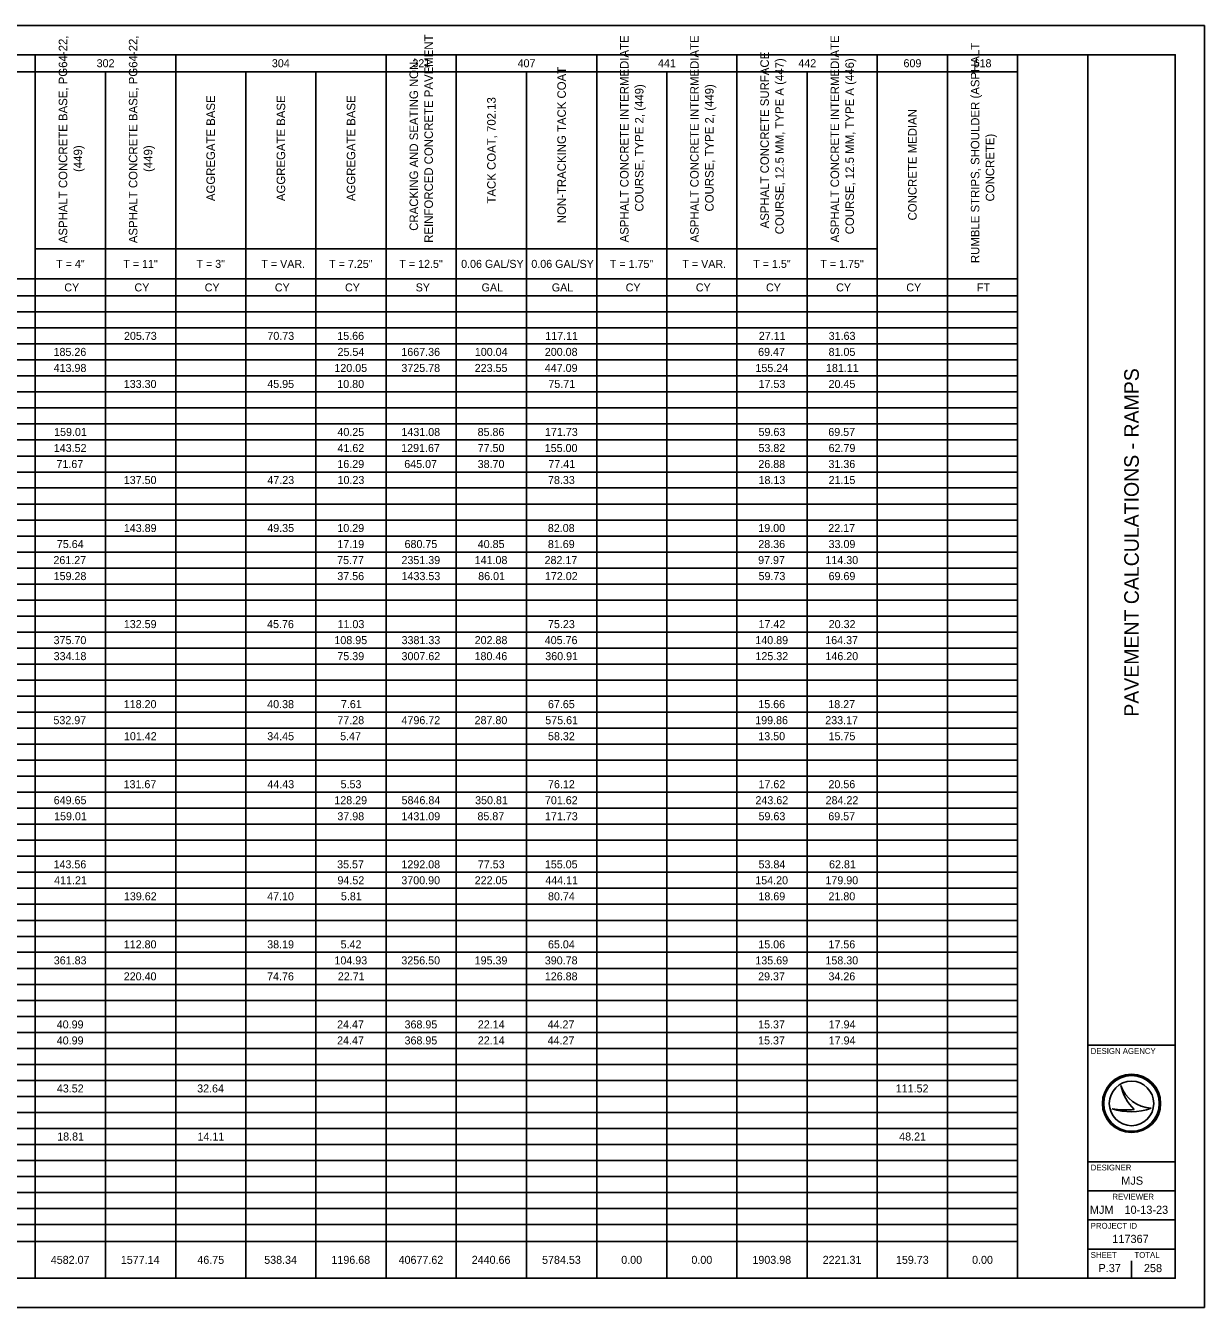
# Model space of a CAD drawing. Extents: x 0 to 34, y 0 to 22.
# Drawn here: x 13.77 to 34, y 0 to 22 of the extents above; entities that cross this region are included whole.
import ezdxf

# ---------------------------------------------------------------- set-up
doc = ezdxf.new("R2010")
doc.units = 0
for name, color, linetype in [('SH_Border', 7, 'Continuous'), ('SH_Cut_Line', 7, 'Continuous'), ('SH_Data', 7, 'Continuous'), ('SH_Text', 7, 'Continuous')]:
    doc.layers.add(name, color=color, linetype=linetype)

msp = doc.modelspace()

# ---------------------------------------------------------------- linework, layer by layer
at = {"layer": 'SH_Border'}
for p, q in [((32, 0.5), (32, 21.5)), ((32, 4.5), (33.5, 4.5)), ((32, 2.5), (33.5, 2.5)), ((32, 2), (33.5, 2)), ((32, 1.5), (33.5, 1.5)), ((32, 1), (33.5, 1))]:
    msp.add_line(p, q, dxfattribs=at)
msp.add_lwpolyline([(1.5, 21.5), (33.5, 21.5), (33.5, 0.5), (1.5, 0.5)], close=True, dxfattribs=at)
at = {"layer": 'SH_Cut_Line'}
msp.add_lwpolyline([(0, 0), (34, 0), (34, 22), (0, 22)], close=True, dxfattribs=at)
at = {"layer": 'SH_Data'}
for p, q in [((32.567, 3.81), (32.567, 3.81)), ((32.417, 3.41), (32.417, 3.41)), ((32.75, 3.5), (32.75, 3.5)), ((33.087, 3.419), (33.087, 3.419)), ((32.375, 0.675), (32.375, 0.675)), ((32.75, 0.5), (32.75, 0.8))]:
    msp.add_line(p, q, dxfattribs=at)
for radius in [0.5, 0.477, 0.477, 0.382]:
    msp.add_circle((32.75, 3.5), radius, dxfattribs=at)
for centre, radius, start, end in [((33.116, 3.998), 0.58, 198.9257, 198.9319), ((33.347, 3.97), 0.796, 191.6379, 191.6421), ((33.116, 3.998), 0.58, 198.9319, 267.1657), ((33.347, 3.97), 0.796, 191.6421, 226.0947), ((32.739, 4.37), 1.013, 251.4576, 290.0832), ((32.648, 4.654), 1.266, 259.4964, 259.4995), ((32.739, 4.37), 1.013, 251.4527, 251.4576), ((32.648, 4.654), 1.266, 259.4995, 276.6672)]:
    msp.add_arc(centre, radius, start, end, dxfattribs=at)
at = {"layer": 'SH_Text'}
for p, q in [((1.5, 21.5), (30.796, 21.5)), ((13.937, 21.5), (13.937, 17.361)), ((16.346, 21.5), (16.346, 17.361)), ((19.958, 21.5), (19.958, 17.361)), ((21.162, 21.5), (21.162, 17.361)), ((23.571, 21.5), (23.571, 17.361)), ((25.979, 21.5), (25.979, 17.361)), ((28.387, 21.5), (28.387, 17.361)), ((29.592, 21.5), (29.592, 17.361)), ((30.796, 21.5), (30.796, 17.361)), ((1.5, 21.209), (30.796, 21.209)), ((15.142, 21.209), (15.142, 17.361)), ((17.55, 21.209), (17.55, 17.361)), ((18.754, 21.209), (18.754, 17.361)), ((22.367, 21.209), (22.367, 17.361)), ((24.775, 21.209), (24.775, 17.361)), ((27.183, 21.209), (27.183, 17.361)), ((13.937, 18.17), (28.387, 18.17)), ((7.142, 17.652), (30.796, 17.652)), ((1.5, 17.361), (30.796, 17.361)), ((1.5, 17.361), (30.796, 17.361)), ((13.937, 17.361), (13.937, 0.5)), ((15.142, 17.361), (15.142, 0.5)), ((16.346, 17.361), (16.346, 0.5)), ((17.55, 17.361), (17.55, 0.5)), ((18.754, 17.361), (18.754, 0.5)), ((19.958, 17.361), (19.958, 0.5)), ((21.162, 17.361), (21.162, 0.5)), ((22.367, 17.361), (22.367, 0.5)), ((23.571, 17.361), (23.571, 0.5)), ((24.775, 17.361), (24.775, 0.5)), ((25.979, 17.361), (25.979, 0.5)), ((27.183, 17.361), (27.183, 0.5)), ((28.387, 17.361), (28.387, 0.5)), ((29.592, 17.361), (29.592, 0.5)), ((30.796, 17.361), (30.796, 0.5)), ((1.5, 17.087), (30.796, 17.087)), ((2.567, 16.812), (30.796, 16.812)), ((2.567, 16.537), (30.796, 16.537)), ((2.567, 16.262), (30.796, 16.262)), ((2.567, 15.987), (30.796, 15.987)), ((2.567, 15.712), (30.796, 15.712)), ((2.567, 15.438), (30.796, 15.438)), ((2.567, 15.163), (30.796, 15.163)), ((2.567, 14.888), (30.796, 14.888)), ((2.567, 14.613), (30.796, 14.613)), ((2.567, 14.338), (30.796, 14.338)), ((2.567, 14.064), (30.796, 14.064)), ((2.567, 13.789), (30.796, 13.789)), ((2.567, 13.514), (30.796, 13.514)), ((2.567, 13.239), (30.796, 13.239)), ((2.567, 12.964), (30.796, 12.964)), ((2.567, 12.689), (30.796, 12.689)), ((2.567, 12.415), (30.796, 12.415)), ((2.567, 12.14), (30.796, 12.14)), ((2.567, 11.865), (30.796, 11.865)), ((2.567, 11.59), (30.796, 11.59)), ((2.567, 11.315), (30.796, 11.315)), ((1.5, 11.04), (30.796, 11.04)), ((1.5, 10.766), (30.796, 10.766)), ((2.567, 10.491), (30.796, 10.491)), ((2.567, 10.216), (30.796, 10.216)), ((2.567, 9.941), (30.796, 9.941)), ((2.567, 9.666), (30.796, 9.666)), ((2.567, 9.391), (30.796, 9.391)), ((2.567, 9.117), (30.796, 9.117)), ((2.567, 8.842), (30.796, 8.842)), ((2.567, 8.567), (30.796, 8.567)), ((2.567, 8.292), (30.796, 8.292)), ((2.567, 8.017), (30.796, 8.017)), ((2.567, 7.742), (30.796, 7.742)), ((2.567, 7.468), (30.796, 7.468)), ((2.567, 7.193), (30.796, 7.193)), ((2.567, 6.918), (30.796, 6.918)), ((2.567, 6.643), (30.796, 6.643)), ((2.567, 6.368), (30.796, 6.368)), ((2.567, 6.094), (30.796, 6.094)), ((2.567, 5.819), (30.796, 5.819)), ((1.5, 5.544), (30.796, 5.544)), ((1.5, 5.269), (30.796, 5.269)), ((2.567, 4.994), (30.796, 4.994)), ((2.567, 4.719), (30.796, 4.719)), ((1.5, 4.445), (30.796, 4.445)), ((1.5, 4.17), (30.796, 4.17)), ((2.567, 3.895), (30.796, 3.895)), ((2.567, 3.62), (30.796, 3.62)), ((2.567, 3.345), (30.796, 3.345)), ((2.567, 3.07), (30.796, 3.07)), ((1.5, 2.796), (30.796, 2.796)), ((1.5, 2.521), (30.796, 2.521)), ((1.5, 2.246), (30.796, 2.246)), ((1.5, 1.971), (30.796, 1.971)), ((1.5, 1.696), (30.796, 1.696)), ((1.5, 1.421), (30.796, 1.421)), ((1.5, 1.13), (30.796, 1.13)), ((1.5, 0.5), (30.796, 0.5))]:
    msp.add_line(p, q, dxfattribs=at)

# ---------------------------------------------------------------- texts
at = {"layer": 'SH_Data'}
msp.add_text('PAVEMENT CALCULATIONS - RAMPS', height=0.25, rotation=90, dxfattribs=at).set_placement((32.875, 10.138))
for s, height, p in [('DESIGN AGENCY', 0.1, (32.05, 4.35)), ('DESIGNER', 0.1, (32.05, 2.35)), ('MJS', 0.14, (32.574, 2.105)), ('REVIEWER', 0.1, (32.422, 1.85)), ('MJM', 0.14, (32.035, 1.605)), ('10-13-23', 0.14, (32.629, 1.605)), ('PROJECT ID', 0.1, (32.05, 1.35)), ('117367', 0.14, (32.42, 1.105)), ('SHEET', 0.1, (32.05, 0.85)), ('TOTAL', 0.1, (32.8, 0.85)), ('P.37', 0.14, (32.183, 0.605)), ('258', 0.14, (32.962, 0.605))]:
    msp.add_text(s, height=height, dxfattribs=at).set_placement(p)
at = {"layer": 'SH_Text'}
for s, height, p in [('ASPHALT CONCRETE BASE, PG64-22, ', 0.14622, (14.485, 18.266)), ('ASPHALT CONCRETE BASE, PG64-22, ', 0.14622, (15.689, 18.266)), ('REINFORCED CONCRETE PAVEMENT', 0.14622, (20.761, 18.273)), ('ASPHALT CONCRETE INTERMEDIATE ', 0.14622, (24.118, 18.28)), ('ASPHALT CONCRETE INTERMEDIATE ', 0.14622, (25.322, 18.28)), ('ASPHALT CONCRETE INTERMEDIATE ', 0.14622, (27.731, 18.28)), ('RUMBLE STRIPS, SHOULDER (ASPHALT ', 0.14622, (30.139, 17.924)), ('CRACKING AND SEATING NON-', 0.14622, (20.506, 18.479)), ('ASPHALT CONCRETE SURFACE ', 0.14622, (26.526, 18.52)), ('COURSE, 12.5 MM, TYPE A (447)', 0.14622, (26.782, 18.419)), ('COURSE, 12.5 MM, TYPE A (446)', 0.14622, (27.986, 18.419)), ('NON-TRACKING TACK COAT', 0.14622, (23.042, 18.609)), ('COURSE, TYPE 2, (449)', 0.14622, (24.374, 18.81)), ('COURSE, TYPE 2, (449)', 0.14622, (25.578, 18.81)), ('AGGREGATE BASE', 0.14622, (17.021, 18.988)), ('AGGREGATE BASE', 0.14622, (18.225, 18.988)), ('AGGREGATE BASE', 0.14622, (19.429, 18.988)), ('TACK COAT, 702.13', 0.14622, (21.838, 18.947)), ('CONCRETE MEDIAN', 0.14622, (29.063, 18.656)), ('CONCRETE)', 0.1462, (30.395, 18.982)), ('(449)', 0.1462, (14.741, 19.489)), ('(449)', 0.1462, (15.945, 19.489))]:
    msp.add_text(s, height=height, rotation=90, dxfattribs=at).set_placement(p)
for s, height, p in [('302', 0.1374, (14.99, 21.286)), ('304', 0.1374, (17.997, 21.286)), ('321', 0.1374, (20.408, 21.286)), ('407', 0.1374, (22.214, 21.286)), ('441', 0.1374, (24.623, 21.286)), ('442', 0.1374, (27.032, 21.286)), ('609', 0.1374, (28.837, 21.286)), ('618', 0.1374, (30.04, 21.286)), ('T = 4"', 0.1374, (14.295, 17.842)), ('T = 11"', 0.1374, (15.447, 17.842)), ('T = 3"', 0.1374, (16.703, 17.842)), ('T = VAR.', 0.1374, (17.817, 17.842)), ('T = 7.25"', 0.1374, (18.98, 17.842)), ('T = 12.5"', 0.1374, (20.185, 17.842)), ('0.06 GAL/SY', 0.13741, (21.245, 17.842)), ('0.06 GAL/SY', 0.13741, (22.45, 17.842)), ('T = 1.75"', 0.1374, (23.797, 17.842)), ('T = VAR.', 0.1374, (25.042, 17.842)), ('T = 1.5"', 0.1374, (26.258, 17.842)), ('T = 1.75"', 0.1374, (27.41, 17.842)), ('CY', 0.1374, (14.435, 17.438)), ('CY', 0.1374, (15.639, 17.438)), ('CY', 0.1374, (16.844, 17.438)), ('CY', 0.1374, (18.048, 17.438)), ('CY', 0.1374, (19.252, 17.438)), ('SY', 0.1374, (20.465, 17.438)), ('GAL', 0.1374, (21.596, 17.438)), ('GAL', 0.1374, (22.801, 17.438)), ('CY', 0.1374, (24.069, 17.438)), ('CY', 0.1374, (25.273, 17.438)), ('CY', 0.1374, (26.477, 17.438)), ('CY', 0.1374, (27.681, 17.438)), ('CY', 0.1374, (28.885, 17.438)), ('FT', 0.1374, (30.096, 17.438)), ('205.73', 0.1374, (15.459, 16.606)), ('70.73', 0.1374, (17.92, 16.606)), ('15.66', 0.1374, (19.12, 16.606)), ('117.11', 0.1374, (22.689, 16.606)), ('27.11', 0.1374, (26.354, 16.606)), ('31.63', 0.1374, (27.553, 16.606)), ('185.26', 0.1374, (14.25, 16.331)), ('25.54', 0.1374, (19.124, 16.331)), ('1667.36', 0.1374, (20.219, 16.331)), ('100.04', 0.1374, (21.48, 16.331)), ('200.08', 0.1374, (22.681, 16.331)), ('69.47', 0.1374, (26.342, 16.331)), ('81.05', 0.1374, (27.551, 16.331)), ('413.98', 0.1374, (14.252, 16.056)), ('120.05', 0.1374, (19.07, 16.056)), ('3725.78', 0.1374, (20.22, 16.056)), ('223.55', 0.1374, (21.478, 16.056)), ('447.09', 0.1374, (22.681, 16.056)), ('155.24', 0.1374, (26.296, 16.056)), ('181.11', 0.1374, (27.506, 16.056)), ('133.30', 0.1374, (15.455, 15.781)), ('45.95', 0.1374, (17.918, 15.781)), ('10.80', 0.1374, (19.12, 15.781)), ('75.71', 0.1374, (22.742, 15.781)), ('17.53', 0.1374, (26.349, 15.781)), ('20.45', 0.1374, (27.551, 15.781)), ('159.01', 0.1374, (14.26, 14.957)), ('40.25', 0.1374, (19.122, 14.957)), ('1431.08', 0.1374, (20.22, 14.957)), ('85.86', 0.1374, (21.528, 14.957)), ('171.73', 0.1374, (22.684, 14.957)), ('59.63', 0.1374, (26.349, 14.957)), ('69.57', 0.1374, (27.546, 14.957)), ('143.52', 0.1374, (14.254, 14.682)), ('41.62', 0.1374, (19.123, 14.682)), ('1291.67', 0.1374, (20.216, 14.682)), ('77.50', 0.1374, (21.529, 14.682)), ('155.00', 0.1374, (22.68, 14.682)), ('53.82', 0.1374, (26.348, 14.682)), ('62.79', 0.1374, (27.551, 14.682)), ('71.67', 0.1374, (14.3, 14.407)), ('16.29', 0.1374, (19.121, 14.407)), ('645.07', 0.1374, (20.269, 14.407)), ('38.70', 0.1374, (21.529, 14.407)), ('77.41', 0.1374, (22.742, 14.407)), ('26.88', 0.1374, (26.346, 14.407)), ('31.36', 0.1374, (27.549, 14.407)), ('137.50', 0.1374, (15.455, 14.132)), ('47.23', 0.1374, (17.92, 14.132)), ('10.23', 0.1374, (19.124, 14.132)), ('78.33', 0.1374, (22.736, 14.132)), ('18.13', 0.1374, (26.349, 14.132)), ('21.15', 0.1374, (27.551, 14.132)), ('143.89', 0.1374, (15.456, 13.308)), ('49.35', 0.1374, (17.918, 13.308)), ('10.29', 0.1374, (19.121, 13.308)), ('82.08', 0.1374, (22.733, 13.308)), ('19.00', 0.1374, (26.345, 13.308)), ('22.17', 0.1374, (27.546, 13.308)), ('75.64', 0.1374, (14.307, 13.033)), ('17.19', 0.1374, (19.121, 13.033)), ('680.75', 0.1374, (20.274, 13.033)), ('40.85', 0.1374, (21.53, 13.033)), ('81.69', 0.1374, (22.734, 13.033)), ('28.36', 0.1374, (26.345, 13.033)), ('33.09', 0.1374, (27.551, 13.033)), ('261.27', 0.1374, (14.248, 12.758)), ('75.77', 0.1374, (19.117, 12.758)), ('2351.39', 0.1374, (20.221, 12.758)), ('141.08', 0.1374, (21.477, 12.758)), ('282.17', 0.1374, (22.677, 12.758)), ('97.97', 0.1374, (26.342, 12.758)), ('114.30', 0.1374, (27.497, 12.758)), ('159.28', 0.1374, (14.252, 12.483)), ('37.56', 0.1374, (19.12, 12.483)), ('1433.53', 0.1374, (20.223, 12.483)), ('86.01', 0.1374, (21.538, 12.483)), ('172.02', 0.1374, (22.683, 12.483)), ('59.73', 0.1374, (26.349, 12.483)), ('69.69', 0.1374, (27.551, 12.483)), ('132.59', 0.1374, (15.456, 11.659)), ('45.76', 0.1374, (17.915, 11.659)), ('11.03', 0.1374, (19.124, 11.659)), ('75.23', 0.1374, (22.736, 11.659)), ('17.42', 0.1374, (26.348, 11.659)), ('20.32', 0.1374, (27.553, 11.659)), ('375.70', 0.1374, (14.251, 11.384)), ('108.95', 0.1374, (19.07, 11.384)), ('3381.33', 0.1374, (20.223, 11.384)), ('202.88', 0.1374, (21.477, 11.384)), ('405.76', 0.1374, (22.68, 11.384)), ('140.89', 0.1374, (26.294, 11.384)), ('164.37', 0.1374, (27.494, 11.384)), ('334.18', 0.1374, (14.252, 11.109)), ('75.39', 0.1374, (19.121, 11.109)), ('3007.62', 0.1374, (20.222, 11.109)), ('180.46', 0.1374, (21.475, 11.109)), ('360.91', 0.1374, (22.689, 11.109)), ('125.32', 0.1374, (26.296, 11.109)), ('146.20', 0.1374, (27.497, 11.109)), ('118.20', 0.1374, (15.455, 10.285)), ('40.38', 0.1374, (17.917, 10.285)), ('7.61', 0.1374, (19.182, 10.285)), ('67.65', 0.1374, (22.735, 10.285)), ('15.66', 0.1374, (26.345, 10.285)), ('18.27', 0.1374, (27.546, 10.285)), ('532.97', 0.1374, (14.248, 10.01)), ('77.28', 0.1374, (19.121, 10.01)), ('4796.72', 0.1374, (20.222, 10.01)), ('287.80', 0.1374, (21.476, 10.01)), ('575.61', 0.1374, (22.689, 10.01)), ('199.86', 0.1374, (26.292, 10.01)), ('233.17', 0.1374, (27.494, 10.01)), ('101.42', 0.1374, (15.458, 9.735)), ('34.45', 0.1374, (17.918, 9.735)), ('5.47', 0.1374, (19.169, 9.735)), ('58.32', 0.1374, (22.736, 9.735)), ('13.50', 0.1374, (26.345, 9.735)), ('15.75', 0.1374, (27.551, 9.735)), ('131.67', 0.1374, (15.452, 8.911)), ('44.43', 0.1374, (17.92, 8.911)), ('5.53', 0.1374, (19.176, 8.911)), ('76.12', 0.1374, (22.736, 8.911)), ('17.62', 0.1374, (26.348, 8.911)), ('20.56', 0.1374, (27.549, 8.911)), ('649.65', 0.1374, (14.253, 8.636)), ('128.29', 0.1374, (19.069, 8.636)), ('5846.84', 0.1374, (20.223, 8.636)), ('350.81', 0.1374, (21.485, 8.636)), ('701.62', 0.1374, (22.683, 8.636)), ('243.62', 0.1374, (26.296, 8.636)), ('284.22', 0.1374, (27.5, 8.636)), ('159.01', 0.1374, (14.26, 8.361)), ('37.98', 0.1374, (19.121, 8.361)), ('1431.09', 0.1374, (20.221, 8.361)), ('85.87', 0.1374, (21.525, 8.361)), ('171.73', 0.1374, (22.684, 8.361)), ('59.63', 0.1374, (26.349, 8.361)), ('69.57', 0.1374, (27.546, 8.361)), ('143.56', 0.1374, (14.25, 7.536)), ('35.57', 0.1374, (19.117, 7.536)), ('1292.08', 0.1374, (20.22, 7.536)), ('77.53', 0.1374, (21.532, 7.536)), ('155.05', 0.1374, (22.682, 7.536)), ('53.84', 0.1374, (26.349, 7.536)), ('62.81', 0.1374, (27.559, 7.536)), ('411.21', 0.1374, (14.26, 7.262)), ('94.52', 0.1374, (19.123, 7.262)), ('3700.90', 0.1374, (20.219, 7.262)), ('222.05', 0.1374, (21.478, 7.262)), ('444.11', 0.1374, (22.689, 7.262)), ('154.20', 0.1374, (26.293, 7.262)), ('179.90', 0.1374, (27.497, 7.262)), ('139.62', 0.1374, (15.458, 6.987)), ('47.10', 0.1374, (17.916, 6.987)), ('5.81', 0.1374, (19.182, 6.987)), ('80.74', 0.1374, (22.736, 6.987)), ('18.69', 0.1374, (26.347, 6.987)), ('21.80', 0.1374, (27.549, 6.987)), ('112.80', 0.1374, (15.455, 6.162)), ('38.19', 0.1374, (17.917, 6.162)), ('5.42', 0.1374, (19.176, 6.162)), ('65.04', 0.1374, (22.736, 6.162)), ('15.06', 0.1374, (26.345, 6.162)), ('17.56', 0.1374, (27.549, 6.162)), ('361.83', 0.1374, (14.254, 5.887)), ('104.93', 0.1374, (19.071, 5.887)), ('3256.50', 0.1374, (20.219, 5.887)), ('195.39', 0.1374, (21.477, 5.887)), ('390.78', 0.1374, (22.681, 5.887)), ('135.69', 0.1374, (26.294, 5.887)), ('158.30', 0.1374, (27.497, 5.887)), ('220.40', 0.1374, (15.455, 5.613)), ('74.76', 0.1374, (17.915, 5.613)), ('22.71', 0.1374, (19.129, 5.613)), ('126.88', 0.1374, (22.681, 5.613)), ('29.37', 0.1374, (26.342, 5.613)), ('34.26', 0.1374, (27.549, 5.613)), ('40.99', 0.1374, (14.305, 4.788)), ('24.47', 0.1374, (19.117, 4.788)), ('368.95', 0.1374, (20.274, 4.788)), ('22.14', 0.1374, (21.532, 4.788)), ('44.27', 0.1374, (22.729, 4.788)), ('15.37', 0.1374, (26.342, 4.788)), ('17.94', 0.1374, (27.553, 4.788)), ('40.99', 0.1374, (14.305, 4.513)), ('24.47', 0.1374, (19.117, 4.513)), ('368.95', 0.1374, (20.274, 4.513)), ('22.14', 0.1374, (21.532, 4.513)), ('44.27', 0.1374, (22.729, 4.513)), ('15.37', 0.1374, (26.342, 4.513)), ('17.94', 0.1374, (27.553, 4.513)), ('43.52', 0.1374, (14.307, 3.689)), ('32.64', 0.1374, (16.715, 3.689)), ('111.52', 0.1374, (28.704, 3.689)), ('18.81', 0.1374, (14.313, 2.864)), ('14.11', 0.1374, (16.721, 2.864)), ('48.21', 0.1374, (28.763, 2.864)), ('4582.07', 0.1374, (14.203, 0.747)), ('1577.14', 0.1374, (15.405, 0.747)), ('46.75', 0.1374, (16.718, 0.747)), ('538.34', 0.1374, (17.866, 0.747)), ('1196.68', 0.1374, (19.019, 0.747)), ('40677.62', 0.1374, (20.172, 0.747)), ('2440.66', 0.1374, (21.427, 0.747)), ('5784.53', 0.1374, (22.634, 0.747)), ('0.00', 0.1374, (23.993, 0.747)), ('0.00', 0.1374, (25.197, 0.747)), ('1903.98', 0.1374, (26.244, 0.747)), ('2221.31', 0.1374, (27.45, 0.747)), ('159.73', 0.1374, (28.707, 0.747)), ('0.00', 0.1374, (30.014, 0.747))]:
    msp.add_text(s, height=height, dxfattribs=at).set_placement(p)

doc.saveas('drawing.dxf')
